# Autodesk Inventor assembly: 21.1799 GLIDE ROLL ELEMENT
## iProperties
Created: 2007-05
Part Number: 21.1799 GLIDE ROLL ELEMENT
Document SubType Name: Assembly
Designer: Andy Moles
Author: Andy Moles
